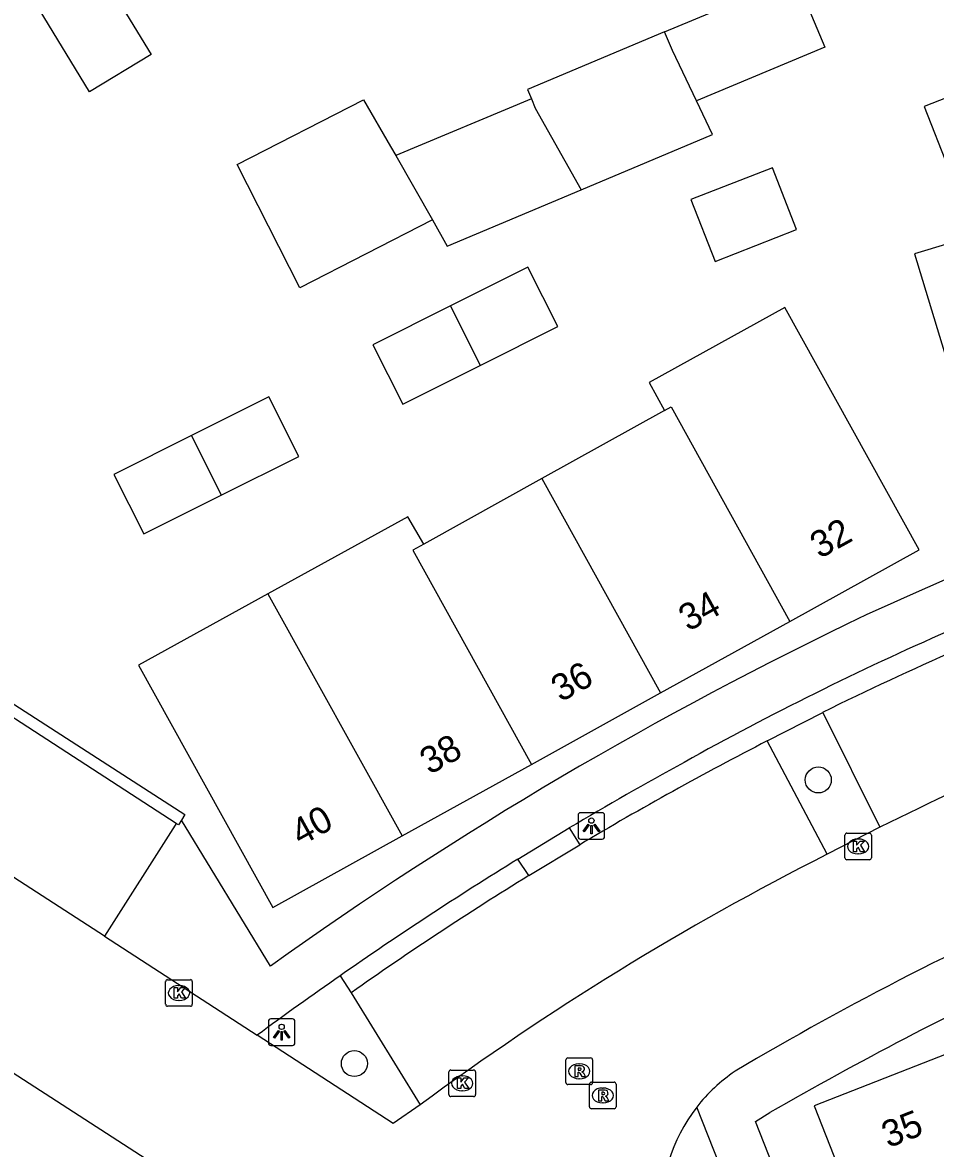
# Model space of a CAD drawing. Extents: x 160158 to 160921, y 381517 to 382041.
# Drawn here: x 160397.49 to 160431.78, y 381621.86 to 381664.16 of the extents above; entities that cross this region are included whole.
import ezdxf

# ---------------------------------------------------------------- set-up
doc = ezdxf.new("R2010")
doc.units = 0
for name, color, linetype in [('IMGEO_Boom', 7, 'Continuous'), ('IMGEO_Haag', 7, 'Continuous'), ('IMGEO_Kolk', 7, 'Continuous'), ('IMGEO_Lichtpunt', 7, 'Continuous'), ('IMGEO_Pand', 7, 'Continuous'), ('IMGEO_Pand_nummerreeks', 7, 'Continuous'), ('IMGEO_Parkeervlak_open', 7, 'Continuous'), ('IMGEO_Rijbaan_lokaal_open', 7, 'Continuous'), ('IMGEO_Rioolput', 7, 'Continuous'), ('IMGEO_Voetpad_open', 7, 'Continuous')]:
    doc.layers.add(name, color=color, linetype=linetype)

msp = doc.modelspace()

# ---------------------------------------------------------------- linework, layer by layer
at = {"layer": 'IMGEO_Boom'}
for centre in [(160427.375, 381635.708), (160409.95, 381625.053)]:
    msp.add_circle(centre, 0.489, dxfattribs=at)
at = {"layer": 'IMGEO_Haag'}
for points in [[(160391.362, 381642.286), (160403.578, 381634.406), (160403.453, 381634.202)], [(160425.457, 381637.176), (160427.539, 381638.244)], [(160409.416, 381628.353), (160409.834, 381627.714)]]:
    msp.add_lwpolyline(points, dxfattribs=at)
at = {"layer": 'IMGEO_Kolk'}
for p, q in [((160428.371, 381632.784), (160428.371, 381633.636)), ((160428.446, 381633.71), (160429.298, 381633.71)), ((160429.372, 381633.636), (160429.372, 381632.784)), ((160428.859, 381633.49), (160428.884, 381633.49)), ((160429.298, 381632.71), (160428.446, 381632.71)), ((160428.882, 381632.93), (160428.857, 381632.93)), ((160402.863, 381627.279), (160402.863, 381628.131)), ((160402.938, 381628.205), (160403.79, 381628.205)), ((160403.864, 381628.131), (160403.864, 381627.279)), ((160403.351, 381627.985), (160403.376, 381627.985)), ((160403.79, 381627.205), (160402.938, 381627.205)), ((160403.374, 381627.425), (160403.349, 381627.425)), ((160413.501, 381623.885), (160413.501, 381624.737)), ((160413.576, 381624.811), (160414.428, 381624.811)), ((160414.502, 381624.737), (160414.502, 381623.885)), ((160413.989, 381624.591), (160414.014, 381624.591)), ((160414.428, 381623.811), (160413.576, 381623.811)), ((160414.012, 381624.031), (160413.987, 381624.031))]:
    msp.add_line(p, q, dxfattribs=at)
for points in [[(160428.371, 381632.784), (160428.371, 381633.636)], [(160428.446, 381633.71), (160429.298, 381633.71)], [(160429.372, 381633.636), (160429.372, 381632.784)], [(160428.692, 381633.41), (160428.815, 381633.41), (160428.815, 381633.259), (160428.945, 381633.41), (160429.109, 381633.41), (160428.963, 381633.259), (160429.116, 381633.01), (160428.964, 381633.01), (160428.879, 381633.174), (160428.815, 381633.107), (160428.815, 381633.01), (160428.692, 381633.01), (160428.692, 381633.41)], [(160429.298, 381632.71), (160428.446, 381632.71)], [(160402.863, 381627.279), (160402.863, 381628.131)], [(160402.938, 381628.205), (160403.79, 381628.205)], [(160403.864, 381628.131), (160403.864, 381627.279)], [(160403.184, 381627.905), (160403.307, 381627.905), (160403.307, 381627.754), (160403.437, 381627.905), (160403.601, 381627.905), (160403.455, 381627.754), (160403.608, 381627.505), (160403.456, 381627.505), (160403.371, 381627.669), (160403.307, 381627.602), (160403.307, 381627.505), (160403.184, 381627.505), (160403.184, 381627.905)], [(160403.79, 381627.205), (160402.938, 381627.205)], [(160413.501, 381623.885), (160413.501, 381624.737)], [(160413.576, 381624.811), (160414.428, 381624.811)], [(160414.502, 381624.737), (160414.502, 381623.885)], [(160413.822, 381624.511), (160413.945, 381624.511), (160413.945, 381624.36), (160414.075, 381624.511), (160414.239, 381624.511), (160414.093, 381624.36), (160414.246, 381624.111), (160414.094, 381624.111), (160414.009, 381624.275), (160413.945, 381624.208), (160413.945, 381624.111), (160413.822, 381624.111), (160413.822, 381624.511)], [(160414.428, 381623.811), (160413.576, 381623.811)]]:
    msp.add_lwpolyline(points, dxfattribs=at)
for centre, start, end in [((160428.448, 381633.634), 91.552, 178.448), ((160428.448, 381633.634), 91.552, 178.448), ((160429.296, 381633.634), 1.552, 88.448), ((160429.296, 381633.634), 1.552, 88.448), ((160428.448, 381632.786), 181.552, 268.448), ((160428.448, 381632.786), 181.552, 268.448), ((160429.296, 381632.786), 271.552, 358.448), ((160429.296, 381632.786), 271.552, 358.448), ((160402.94, 381628.129), 91.552, 178.448), ((160402.94, 381628.129), 91.552, 178.448), ((160403.788, 381628.129), 1.552, 88.448), ((160403.788, 381628.129), 1.552, 88.448), ((160402.94, 381627.281), 181.552, 268.448), ((160402.94, 381627.281), 181.552, 268.448), ((160403.788, 381627.281), 271.552, 358.448), ((160403.788, 381627.281), 271.552, 358.448), ((160413.578, 381624.735), 91.552, 178.448), ((160413.578, 381624.735), 91.552, 178.448), ((160414.426, 381624.735), 1.552, 88.448), ((160414.426, 381624.735), 1.552, 88.448), ((160413.578, 381623.887), 181.552, 268.448), ((160413.578, 381623.887), 181.552, 268.448), ((160414.426, 381623.887), 271.552, 358.448), ((160414.426, 381623.887), 271.552, 358.448)]:
    msp.add_arc(centre, 0.0765, start, end, dxfattribs=at)
for centre, major_axis, ratio, start_param, end_param in [((160428.858, 381633.21), (-0.387, 0.002), 0.722429, 4.712389, 7.853982), ((160428.883, 381633.21), (-0.39, 0.002), 0.717154, 1.570796, 4.712389), ((160403.35, 381627.705), (-0.387, 0.002), 0.722429, 4.712389, 7.853982), ((160403.375, 381627.705), (-0.39, 0.002), 0.717154, 1.570796, 4.712389), ((160413.988, 381624.311), (-0.387, 0.002), 0.722429, 4.712389, 7.853982), ((160414.013, 381624.311), (-0.39, 0.002), 0.717154, 1.570796, 4.712389)]:
    msp.add_ellipse(centre, major_axis=major_axis, ratio=ratio, start_param=start_param, end_param=end_param, dxfattribs=at)
at = {"layer": 'IMGEO_Lichtpunt'}
for p, q in [((160418.354, 381634.384), (160418.354, 381633.577)), ((160418.354, 381634.384), (160418.354, 381633.577)), ((160419.256, 381634.479), (160418.448, 381634.479)), ((160419.256, 381634.479), (160418.448, 381634.479)), ((160419.35, 381633.577), (160419.35, 381634.384)), ((160419.35, 381633.577), (160419.35, 381634.384)), ((160418.448, 381633.483), (160419.256, 381633.483)), ((160418.448, 381633.483), (160419.256, 381633.483)), ((160407.623, 381626.731), (160406.815, 381626.731)), ((160407.623, 381626.731), (160406.815, 381626.731)), ((160406.721, 381626.636), (160406.721, 381625.829)), ((160406.721, 381626.636), (160406.721, 381625.829)), ((160407.717, 381625.829), (160407.717, 381626.636)), ((160407.717, 381625.829), (160407.717, 381626.636)), ((160406.815, 381625.735), (160407.623, 381625.735)), ((160406.815, 381625.735), (160407.623, 381625.735))]:
    msp.add_line(p, q, dxfattribs=at)
for points in [[(160418.728, 381634.048), (160418.767, 381634.02), (160418.579, 381633.758), (160418.541, 381633.785), (160418.728, 381634.048)], [(160418.83, 381634), (160418.877, 381634), (160418.877, 381633.678), (160418.83, 381633.678), (160418.83, 381634)], [(160418.94, 381634.02), (160418.978, 381634.047), (160419.165, 381633.785), (160419.126, 381633.757), (160418.94, 381634.02)], [(160407.095, 381626.3), (160407.134, 381626.272), (160406.946, 381626.01), (160406.908, 381626.037), (160407.095, 381626.3)], [(160407.197, 381626.252), (160407.244, 381626.252), (160407.244, 381625.93), (160407.197, 381625.93), (160407.197, 381626.252)], [(160407.307, 381626.272), (160407.345, 381626.299), (160407.532, 381626.037), (160407.493, 381626.009), (160407.307, 381626.272)]]:
    msp.add_lwpolyline(points, dxfattribs=at)
for centre in [(160418.853, 381634.182), (160407.22, 381626.434)]:
    msp.add_circle(centre, 0.0994, dxfattribs=at)
for centre, start, end in [((160418.448, 381634.384), 90, 180), ((160418.448, 381634.384), 90, 180), ((160419.256, 381634.384), 0, 90), ((160419.256, 381634.384), 0, 90), ((160418.448, 381633.577), 180, 270), ((160418.448, 381633.577), 180, 270), ((160419.256, 381633.577), 270, 0), ((160419.256, 381633.577), 270, 360), ((160406.815, 381626.636), 90, 180), ((160406.815, 381626.636), 90, 180), ((160407.623, 381626.636), 0, 90), ((160407.623, 381626.636), 0, 90), ((160406.815, 381625.829), 180, 270), ((160406.815, 381625.829), 180, 270), ((160407.623, 381625.829), 270, 0), ((160407.623, 381625.829), 270, 360)]:
    msp.add_arc(centre, 0.0946, start, end, dxfattribs=at)
at = {"layer": 'IMGEO_Pand'}
for points in [[(160398.115, 381664.662), (160400.433, 381666.068), (160402.314, 381662.966), (160399.997, 381661.56), (160398.115, 381664.662)], [(160421.604, 381663.81), (160426.519, 381665.866), (160427.62, 381663.235), (160422.801, 381661.218)], [(160421.604, 381663.81), (160416.45, 381661.653), (160416.598, 381661.302)], [(160422.801, 381661.218), (160421.898, 381663.109), (160421.893, 381663.119), (160421.604, 381663.81)], [(160434.387, 381662.194), (160431.352, 381661.013), (160432.261, 381658.684), (160435.293, 381659.864)], [(160412.887, 381656.754), (160407.905, 381654.191), (160405.545, 381658.829), (160410.298, 381661.259), (160411.312, 381659.503), (160411.503, 381659.17)], [(160416.598, 381661.302), (160411.503, 381659.17)], [(160416.598, 381661.302), (160416.745, 381660.952), (160418.467, 381657.877)], [(160418.467, 381657.877), (160423.403, 381659.958), (160422.801, 381661.218)], [(160411.503, 381659.17), (160412.887, 381656.754)], [(160425.649, 381658.71), (160422.587, 381657.509), (160423.498, 381655.185), (160426.561, 381656.387), (160425.649, 381658.71)], [(160412.887, 381656.754), (160413.438, 381655.757), (160418.467, 381657.877)], [(160436.636, 381655.918), (160436.271, 381657.061), (160430.989, 381655.469), (160434.023, 381645.493), (160439.106, 381647.039)], [(160414.68, 381651.28), (160417.59, 381652.738), (160416.467, 381654.977), (160413.557, 381653.519)], [(160413.557, 381653.519), (160410.647, 381652.061), (160411.769, 381649.822), (160414.68, 381651.28)], [(160413.557, 381653.519), (160414.68, 381651.28)], [(160426.309, 381641.667), (160431.165, 381644.355), (160426.124, 381653.458), (160421.022, 381650.637), (160421.602, 381649.587)], [(160404.954, 381646.407), (160407.864, 381647.865), (160406.742, 381650.105), (160403.832, 381648.647)], [(160421.602, 381649.587), (160416.994, 381647.031)], [(160421.602, 381649.587), (160421.848, 381649.723), (160426.309, 381641.667)], [(160403.832, 381648.647), (160400.922, 381647.188), (160402.044, 381644.949), (160404.954, 381646.407)], [(160403.832, 381648.647), (160404.954, 381646.407)], [(160416.994, 381647.031), (160412.556, 381644.569)], [(160416.994, 381647.031), (160421.453, 381638.979)], [(160412.556, 381644.569), (160411.96, 381645.599), (160406.702, 381642.702)], [(160412.556, 381644.569), (160412.141, 381644.339), (160416.597, 381636.291)], [(160406.702, 381642.702), (160401.847, 381640.026), (160406.885, 381630.915), (160411.741, 381633.603)], [(160406.702, 381642.702), (160411.741, 381633.603)], [(160421.453, 381638.979), (160426.309, 381641.667)], [(160416.597, 381636.291), (160421.453, 381638.979)], [(160411.741, 381633.603), (160416.597, 381636.291)], [(160432.177, 381625.409), (160427.225, 381623.464), (160431.022, 381613.791), (160435.991, 381615.726)]]:
    msp.add_lwpolyline(points, dxfattribs=at)
at = {"layer": 'IMGEO_Parkeervlak_open'}
for points in [[(160403.263, 381634.078), (160391.135, 381641.935), (160391.362, 381642.286)], [(160427.539, 381638.244), (160429.689, 381633.931)], [(160427.708, 381632.917), (160425.457, 381637.176)], [(160409.834, 381627.714), (160412.421, 381623.498)]]:
    msp.add_lwpolyline(points, dxfattribs=at)
for centre, radius, start, end in [((160484.387, 381523.097), 128.415, 113.7903, 116.2758), ((160485.679, 381520.181), 131.585, 117.23664, 120.74117), ((160485.152, 381520.84), 130.747, 121.67297, 125.17402)]:
    msp.add_arc(centre, radius, start, end, dxfattribs=at)
at = {"layer": 'IMGEO_Rijbaan_lokaal_open'}
for points in [[(160400.563, 381629.843), (160387.357, 381638.374)], [(160429.689, 381633.931), (160427.708, 381632.917)], [(160400.563, 381629.843), (160406.303, 381626.118)], [(160390.808, 381628.79), (160390.812, 381628.788), (160403.579, 381620.534)], [(160412.421, 381623.498), (160411.413, 381622.801), (160406.303, 381626.118)]]:
    msp.add_lwpolyline(points, dxfattribs=at)
for centre, radius, start, end in [((160476.357, 381540.973), 104.015, 109.57182, 116.658), ((160484.652, 381523.127), 118.231, 106.15301, 120.72436), ((160476.35, 381536.857), 107.674, 116.85616, 126.42198), ((160427.737, 381619.583), 6.245, 123.97, 142.1226), ((160427.733, 381619.591), 6.238, 142.1558, 225.1672)]:
    msp.add_arc(centre, radius, start, end, dxfattribs=at)
at = {"layer": 'IMGEO_Rioolput'}
for p, q in [((160417.898, 381624.339), (160417.898, 381625.191)), ((160417.973, 381625.265), (160418.825, 381625.265)), ((160418.386, 381625.045), (160418.411, 381625.045)), ((160418.899, 381625.191), (160418.899, 381624.339)), ((160418.825, 381624.265), (160417.973, 381624.265)), ((160418.409, 381624.485), (160418.384, 381624.485)), ((160418.78, 381623.429), (160418.78, 381624.281)), ((160418.855, 381624.355), (160419.707, 381624.355)), ((160419.781, 381624.281), (160419.781, 381623.429)), ((160419.268, 381624.135), (160419.293, 381624.135)), ((160419.707, 381623.355), (160418.855, 381623.355)), ((160419.291, 381623.575), (160419.266, 381623.575))]:
    msp.add_line(p, q, dxfattribs=at)
for points in [[(160417.898, 381624.339), (160417.898, 381625.191)], [(160417.973, 381625.265), (160418.825, 381625.265)], [(160418.899, 381625.191), (160418.899, 381624.339)], [(160418.487, 381624.963), (160418.235, 381624.965), (160418.235, 381624.565)], [(160418.235, 381624.565), (160418.359, 381624.565), (160418.359, 381624.727), (160418.37, 381624.727)], [(160418.413, 381624.884), (160418.359, 381624.884), (160418.359, 381624.803)], [(160418.359, 381624.803), (160418.411, 381624.803)], [(160418.417, 381624.698), (160418.488, 381624.565), (160418.628, 381624.565), (160418.563, 381624.691)], [(160418.825, 381624.265), (160417.973, 381624.265)], [(160418.78, 381623.429), (160418.78, 381624.281)], [(160418.855, 381624.355), (160419.707, 381624.355)], [(160419.781, 381624.281), (160419.781, 381623.429)], [(160419.369, 381624.053), (160419.117, 381624.055), (160419.117, 381623.655)], [(160419.117, 381623.655), (160419.241, 381623.655), (160419.241, 381623.817), (160419.252, 381623.817)], [(160419.295, 381623.974), (160419.241, 381623.974), (160419.241, 381623.893)], [(160419.241, 381623.893), (160419.293, 381623.893)], [(160419.299, 381623.788), (160419.37, 381623.655), (160419.51, 381623.655), (160419.445, 381623.781)], [(160419.707, 381623.355), (160418.855, 381623.355)]]:
    msp.add_lwpolyline(points, dxfattribs=at)
for centre, radius, start, end in [((160417.975, 381625.189), 0.0765, 91.552, 178.448), ((160417.975, 381625.189), 0.0765, 91.552, 178.448), ((160418.823, 381625.189), 0.0765, 1.552, 88.448), ((160418.823, 381625.189), 0.0765, 1.552, 88.448), ((160418.369, 381624.674), 0.0533, 26.0293, 88.6989), ((160418.395, 381624.992), 0.19, 274.7715, 282.9687), ((160418.419, 381624.788), 0.0964, 77.0061, 93.1865), ((160418.433, 381624.845), 0.0378, 276.6634, 79.6772), ((160418.486, 381624.853), 0.109, 350.3612, 89.416), ((160418.484, 381624.853), 0.112, 277.5842, 350.9817), ((160418.468, 381624.638), 0.108, 29.5134, 73.7905), ((160417.975, 381624.341), 0.0765, 181.552, 268.448), ((160417.975, 381624.341), 0.0765, 181.552, 268.448), ((160418.857, 381624.279), 0.0765, 91.552, 178.448), ((160418.857, 381624.279), 0.0765, 91.552, 178.448), ((160418.823, 381624.341), 0.0765, 271.552, 358.448), ((160418.823, 381624.341), 0.0765, 271.552, 358.448), ((160419.705, 381624.279), 0.0765, 1.552, 88.448), ((160419.705, 381624.279), 0.0765, 1.552, 88.448), ((160419.251, 381623.764), 0.0533, 26.0293, 88.6989), ((160419.277, 381624.082), 0.19, 274.7715, 282.9687), ((160419.301, 381623.878), 0.0964, 77.0061, 93.1865), ((160419.315, 381623.935), 0.0378, 276.6634, 79.6772), ((160419.368, 381623.943), 0.109, 350.3612, 89.416), ((160419.366, 381623.943), 0.112, 277.5842, 350.9817), ((160419.35, 381623.728), 0.108, 29.5134, 73.7905), ((160418.857, 381623.431), 0.0765, 181.552, 268.448), ((160418.857, 381623.431), 0.0765, 181.552, 268.448), ((160419.705, 381623.431), 0.0765, 271.552, 358.448), ((160419.705, 381623.431), 0.0765, 271.552, 358.448)]:
    msp.add_arc(centre, radius, start, end, dxfattribs=at)
for centre, major_axis, ratio, start_param, end_param in [((160418.385, 381624.765), (-0.387, 0.002), 0.722429, 4.712389, 7.853982), ((160418.41, 381624.765), (-0.39, 0.002), 0.717154, 1.570796, 4.712389), ((160419.267, 381623.855), (-0.387, 0.002), 0.722429, 4.712389, 7.853982), ((160419.292, 381623.855), (-0.39, 0.002), 0.717154, 1.570796, 4.712389)]:
    msp.add_ellipse(centre, major_axis=major_axis, ratio=ratio, start_param=start_param, end_param=end_param, dxfattribs=at)
at = {"layer": 'IMGEO_Voetpad_open'}
for points in [[(160403.263, 381634.078), (160403.222, 381634.014), (160400.563, 381629.843)], [(160403.453, 381634.202), (160403.342, 381634.026), (160403.263, 381634.078)], [(160406.797, 381628.714), (160403.453, 381634.202)], [(160416.095, 381632.737), (160418.023, 381633.905)], [(160418.023, 381633.905), (160418.418, 381633.276)], [(160416.501, 381632.114), (160418.418, 381633.276)], [(160416.501, 381632.114), (160416.095, 381632.737)], [(160427.338, 381611.987), (160422.807, 381623.418)], [(160435.012, 381607.897), (160434.955, 381607.95), (160428.842, 381613.142), (160425.011, 381622.871), (160425.558, 381623.211)]]:
    msp.add_lwpolyline(points, dxfattribs=at)
for centre, radius, start, end in [((160488.845, 381512.009), 142.948, 104.01054, 114.65965), ((160492.712, 381508.556), 147.714, 115.46429, 125.56554), ((160480.196, 381532.352), 119.029, 113.73395, 119.08731), ((160489.797, 381513.415), 140.247, 118.75399, 120.7816), ((160490.755, 381511.713), 142.2, 121.67057, 124.89007), ((160497.465, 381498.12), 144.286, 115.29103, 119.892), ((160490.828, 381511.673), 142.275, 124.90505, 126.44839)]:
    msp.add_arc(centre, radius, start, end, dxfattribs=at)

# ---------------------------------------------------------------- texts
at = {"layer": 'IMGEO_Pand_nummerreeks'}
for s, rotation, p in [('32', 28.9687, (160427.428, 381644.001)), ('34', 28.9687, (160422.491, 381641.268)), ('36', 28.9687, (160417.701, 381638.616)), ('38', 28.9687, (160412.772, 381635.888)), ('40', 28.9687, (160407.931, 381633.209)), ('35', 21.4458, (160430.002, 381621.869))]:
    msp.add_text(s, height=1, rotation=rotation, dxfattribs=at).set_placement(p)

doc.saveas('drawing.dxf')
